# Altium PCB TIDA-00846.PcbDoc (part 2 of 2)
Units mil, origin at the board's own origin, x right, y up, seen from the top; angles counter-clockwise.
Board outline 4950 x 3450 mil, 2 copper layers (Top Layer, Bottom Layer), stack 62 mil thick; 90 components, 50 nets, 307 pads, 480 vias.
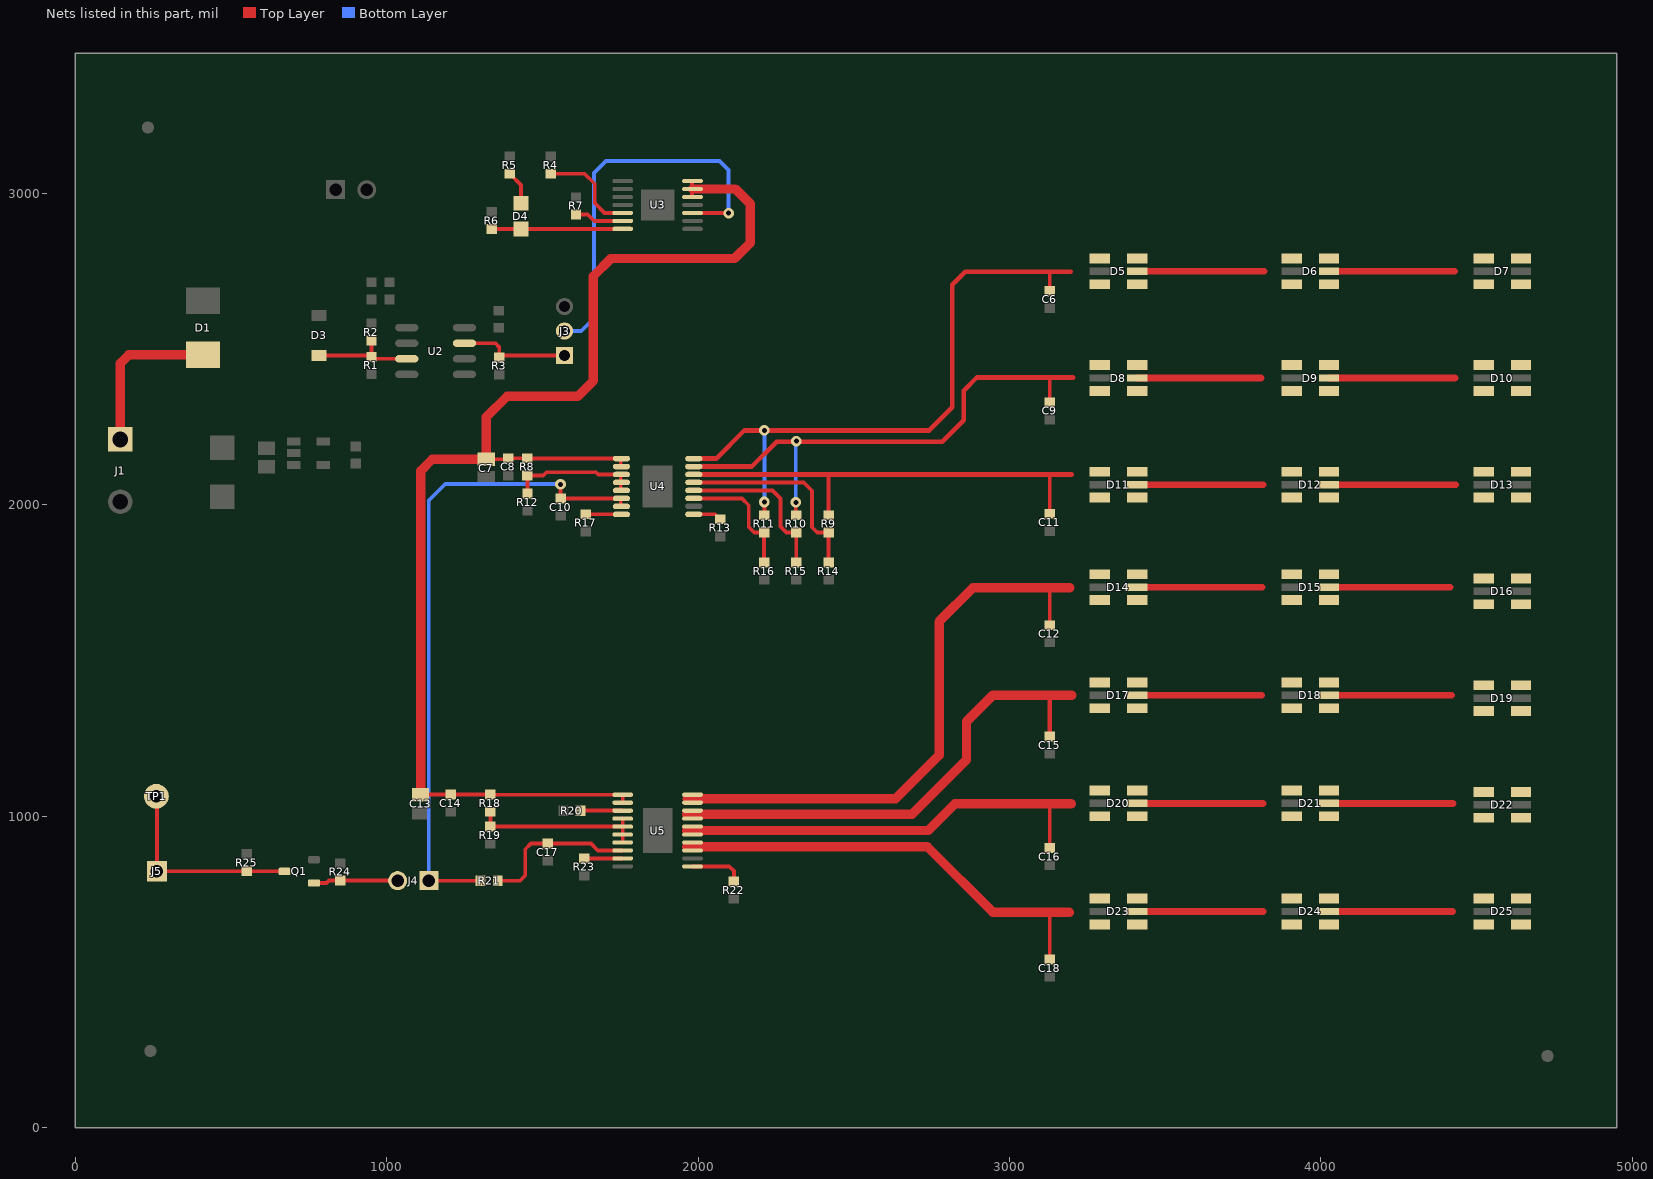
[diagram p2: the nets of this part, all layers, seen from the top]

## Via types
v1: diameter 34, hole 16, Top Layer to Bottom Layer, 455 vias
v2: diameter 15.75, hole 7.87, Top Layer to Bottom Layer, 10 vias
v3: diameter 19.68, hole 7.87, Top Layer to Bottom Layer, 8 vias
v4: diameter 30, hole 18, Top Layer to Bottom Layer, 7 vias

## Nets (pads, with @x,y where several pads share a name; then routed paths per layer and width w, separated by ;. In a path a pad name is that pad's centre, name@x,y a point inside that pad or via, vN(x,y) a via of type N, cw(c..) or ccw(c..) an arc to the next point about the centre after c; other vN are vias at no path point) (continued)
NetC6_1: C6.1 D5.1 D5.3 D5.4 D5.6 R11.2 U4.16 | length 2023.6
  Top Layer w12: R11.2@2212,1966.56 2213,1967.56 v1(2213,2009) ; C6.1@3129,2687.56 3129,2748
  Top Layer w15: U4.16@1986.14,2148.65 2058.65,2148.65 2149,2239 v1(2213,2239) 2742,2239 2816,2313 2816,2707 2858,2749 3197,2749
  Bottom Layer w12: v1(2213,2009) v1(2213,2239)
NetC7_1: C7.1 C8.1 C13.1 C14.1 R8.2 R18.2 U3.5 U3.6 U3.7 U4.1 U4.2 U5.1 U5.2 | length 4121.1
  Top Layer w12: C13.1@1109,1069.53 1205.05,1069.53 C14.1@1205.2,1069.68 1332.88,1069.68 R18.2@1333,1069.56 1333.4,1069.16 U5.1@1757.8,1069.16 ; C7.1@1319.89,2146.61 C7.1@1320,2146.61 ; C7.1@1347.45,2146.61 1386.86,2146.61 C8.1@1389.89,2149.65 1389.98,2149.56 R8.2@1451,2149.56 1451.91,2148.65 U4.1@1751.75,2148.65 ; U4.2@1751.75,2123.06 U4.1@1751.75,2148.65 ; U4.1@1753.86,2148.65 U4.1@1751.75,2148.65 ; U5.2@1757.8,1043.57 1757.8,1062.13 ; U3.5@1980.2,2988.59 U3.7@1980.2,3039.77
  Top Layer w30: C13.1@1109,1091.18 1109,2109 1146.61,2146.61 C7.1@1319.89,2146.61 ; C7.1@1319.89,2168.27 1319.89,2281.89 1387,2349 1614,2349 1663,2398 1663,2734 1720,2791 2117,2791 2168,2842 2168,2966 2119.82,3014.18 U3.6@1982.2,3014.18 ; C7.1@1320,2142.68 C7.1@1320,2146.61
NetC9_1: C9.1 D8.1 D8.3 D8.4 D8.6 R10.2 U4.15 | length 1712.7
  Top Layer w12: v1(2314,2008) 2314,1968.06 R10.2@2315.5,1966.56 ; v1@2314,2203 v1(2315.5,2204.5) ; C9.1@3129,2329.56 3129,2409
  Top Layer w15: U4.15@1986.14,2123.06 2172.06,2123.06 2252,2203 2314,2203 2784,2203 2853,2272 2853,2367 2895,2409 3129,2409 3204,2409
  Bottom Layer w12: v1(2314,2008) 2314,2203 v1(2315.5,2204.5)
NetC10_1: C10.1 J4.1 R21.2 U4.6 U4.7 | length 2085.4
  Top Layer w12: J4.1@1135,793 R21.2@1285.69,793 ; v1(1558,2066) 1558,2021.56 C10.1@1559,2020.56 1559.14,2020.7 U4.6@1751.75,2020.7 ; U4.7@1751.75,1995.11 U4.6@1751.75,2020.7 ; U4.6@1753.86,2020.7 U4.6@1751.75,2020.7
  Bottom Layer w12: J4.1@1135,793 1135,2014 1188,2067 1557,2067 1558,2068 v1(1558,2066)
NetC11_1: C11.1 D11.1 D11.3 D11.4 D11.6 R9.2 U4.14 | length 1469.2
  Top Layer w12: R9.2@2419,1966.56 2419,2096.47 ; C11.1@3129,1971.56 3129,2096.47
  Top Layer w15: U4.14@1986.14,2097.47 3200.53,2097.47
NetC12_1: C12.1 D14.1 D14.3 D14.4 D14.6 U5.19 U5.20 | length 1879.6
  Top Layer w12: C12.1@3129,1613.56 3129,1732
  Top Layer w30: 1965,1056 2634,1056 2774,1196 2774,1625 2883,1734 3194,1734
NetC15_1: C15.1 D17.1 D17.3 D17.4 D17.6 U5.17 U5.18 | length 1597.1
  Top Layer w15: C15.1@3129,1255.56 3129,1385
  Top Layer w30: 1963,1006 2687,1006 2862,1181 2862,1304 2947,1389 3200,1389
NetC16_1: C16.1 D20.1 D20.3 D20.4 D20.6 U5.15 U5.16 | length 1412.1
  Top Layer w12: C16.1@3129,897.56 3129,1039
  Top Layer w30: 1963,954 2739,954 2825,1040 3198,1040
NetC17_1: C17.1 R21.1 U5.8 | length 492.6
  Top Layer w12: R21.1@1356.56,793 1428,793 1445,810 1445,894 1463.56,912.56 C17.1@1500.27,912.56 ; C17.1@1517,912.56 1517.56,912 1656,912 1677.98,890.02 U5.8@1757.8,890.02
NetC18_1: C18.1 D23.1 D23.3 D23.4 D23.6 U5.13 U5.14 | length 1466.8
  Top Layer w12: C18.1@3129,539.56 3129,691
  Top Layer w30: 1964,902 2736,902 2946,692 3191,692 3192,691
NetD1_2: D1.2 J1.1 | length 467.5
  Top Layer w30: J1.1@144.25,2210 144.25,2454.25 171.99,2481.99 D1.2@356,2481.99
NetD3_2: D3.2 R1.1 R2.2 U2.7 | length 330.9
  Top Layer w12: D3.2@783,2479.53 947.03,2479.53 R1.1@951,2475.56 957.56,2469 U2.7@1064.48,2469 ; R1.1@951,2482.43 R2.2@951,2527.44
NetD4_1: D4.1 R5.1 | length 86.4
  Top Layer w12: R5.1@1395,3063.49 1431,3027.49 D4.1@1431,2991.96
NetD4_2: D4.2 R6.1 U3.14 | length 422.2
  Top Layer w10: R6.1@1337,2885.44 R6.1@1337.22,2885.66 ; D4.2@1431,2885.66 D4.2@1431.57,2886.23 ; U3.14@1757.01,2885.44 U3.14@1757.8,2886.23
  Top Layer w12: R6.1@1337.22,2885.66 D4.2@1431,2885.66 ; D4.2@1431.57,2886.23 U3.14@1757.8,2886.23
NetD5_2: D5.2 D6.1 D6.3 D6.4 D6.6 | length 407
  Top Layer w22: D5.2@3410.04,2750 3817,2750
NetD6_2: D6.2 D7.1 D7.3 D7.4 D7.6 | length 403.5
  Top Layer w22: D6.2@4026.54,2750 4430,2750
NetD8_2: D8.2 D9.1 D9.3 D9.4 D9.6 | length 397.3
  Top Layer w22: D8.2@3410.04,2407.33 3807.33,2407.33
NetD9_2: D9.2 D10.1 D10.3 D10.4 D10.6 | length 404.8
  Top Layer w22: D9.2@4026.54,2407.33 4431.33,2407.33
NetD11_2: D11.2 D12.1 D12.3 D12.4 D12.6 | length 403.6
  Top Layer w22: D11.2@3410.04,2064.67 3813.67,2064.67
NetD12_2: D12.2 D13.1 D13.3 D13.4 D13.6 | length 406.1
  Top Layer w22: D12.2@4026.54,2064.67 4432.67,2064.67
NetD14_2: D14.2 D15.1 D15.3 D15.4 D15.6 | length 400.5
  Top Layer w22: D14.2@3410.04,1735.5 3810.5,1735.5
NetD15_2: D15.2 D16.1 D16.3 D16.4 D16.6 | length 389
  Top Layer w22: D15.2@4026.54,1735.5 4415.5,1735.5
NetD17_2: D17.2 D18.1 D18.3 D18.4 D18.6 | length 399.3
  Top Layer w22: D17.2@3410.04,1388.33 3809.33,1388.33
NetD18_2: D18.2 D19.1 D19.3 D19.4 D19.6 | length 393.1
  Top Layer w22: D18.2@4026.54,1388.33 4419.67,1388.33
NetD20_2: D20.2 D21.1 D21.3 D21.4 D21.6 | length 404.1
  Top Layer w22: D20.2@3410.04,1041.17 3814.17,1041.17
NetD21_2: D21.2 D22.1 D22.3 D22.4 D22.6 | length 397.6
  Top Layer w22: D21.2@4026.54,1041.17 4424.17,1041.17
NetD23_2: D23.2 D24.1 D24.3 D24.4 D24.6 | length 405
  Top Layer w22: D23.2@3410.04,694 3815,694
NetD24_2: D24.2 D25.1 D25.3 D25.4 D25.6 | length 396.5
  Top Layer w22: D24.2@4026.54,694 4423,694
NetJ3_1: J3.1 R3.2 U2.3 | length 346.5
  Top Layer w10: R3.2@1361,2473.56 R3.2@1366.7,2479.26
  Top Layer w12: U2.3@1249.52,2519 1349,2519 1361,2507 R3.2@1361,2489.31 ; R3.2@1366.7,2479.26 J3.1@1571,2479.26
NetJ3_2: J3.2 U3.3 | length 1292.1
  Top Layer w12: U3.3@1982.2,2937.41 v1@2097.59,2937.41
  Bottom Layer w12: J3.2@1571,2558 1625,2558 1666,2599 1666,3066 1704,3104 2069,3104 2098,3075 v1(2098,2937)
NetJ4_2: J4.2 Q1.1 R24.1 | length 271.7
  Top Layer w12: Q1.1@766.19,785.52 806.52,785.52 814.44,793.44 R24.1@851,793.44 J4.2@1034.56,793.44
NetJ5_1: J5.1 Q1.3 R25.2 TP1.1 | length 647.6
  Top Layer w12: TP1.1@262.44,1061.56 262.44,823.44 R25.2@550,823.44 550.52,822.92 Q1.3@671.7,822.92
NetR4_1: R4.1 U3.12 | length 317.3
  Top Layer w12: R4.1@1527,3063.49 1635.51,3063.49 1668,3031 1668,2969 1699.59,2937.41 U3.12@1755.8,2937.41
NetR7_1: R7.1 U3.13 | length 141.6
  Top Layer w12: 1624.73,2932.44 1645.56,2932.44 1666.18,2911.82 U3.13@1757.8,2911.82
NetR8_1: R8.1 R12.2 U4.3 U4.4 U4.5 | length 421.1
  Top Layer w12: R12.2@1452.21,2036.65 1452.21,2093.23 R8.1@1451,2094.44 1502.44,2094.44 1513,2105 1672,2105 1679.53,2097.47 U4.3@1753,2097.47 ; U4.5@1751.75,2046.29 1751.75,2097.47 U4.3@1753.86,2097.47
NetR9_1: R9.1 R14.2 U4.13 | length 667.1
  Top Layer w12: U4.13@1984,2071.88 2339.12,2071.88 2366,2045 2366,1928 2382.56,1911.44 R9.1@2419,1911.44 R14.2@2419,1814.31
NetR10_1: R10.1 R15.2 U4.12 | length 502.3
  Top Layer w12: U4.12@1986.14,2046.29 2238.71,2046.29 2265,2020 2265,1930 2283.56,1911.44 R10.1@2298.77,1911.44 ; R15.2@2315.5,1830.31 R10.1@2315.5,1911.44
NetR11_1: R11.1 R16.2 U4.11 | length 376.5
  Top Layer w12: U4.11@1986.14,2020.7 2141.3,2020.7 2163,1999 2163,1929 2180.56,1911.44 R11.1@2195.27,1911.44 ; R16.2@2212,1830.31 R11.1@2212,1911.44
NetR13_2: R13.2 U4.9 | length 91.5
  Top Layer w12: U4.9@1986.14,1969.52 2055.04,1969.52 R13.2@2071,1953.56
NetR17_2: R17.2 U4.8 | length 114.9
  Top Layer w12: R17.2@1639,1969.56 1639.04,1969.52 U4.8@1753.86,1969.52
NetR18_1: R18.1 R19.2 U5.4 U5.5 U5.6 U5.7 | length 526.8
  Top Layer w12: R19.2@1333,966.56 1333.24,966.8 U5.5@1757.8,966.8 ; R19.2@1333,982.31 R18.1@1333,1014.44 ; 1757.8,922.64 U5.6@1757.8,941.2 U5.5@1757.8,966.8 ; U5.4@1757.8,992.39 U5.5@1757.8,966.8
NetR20_2: R20.2 U5.3 | length 135.2
  Top Layer w12: R20.2@1622.56,1018 U5.3@1757.8,1017.98
NetR22_2: R22.2 U5.11 | length 156.6
  Top Layer w12: U5.11@1982.2,838.84 2100.16,838.84 2115,824 R22.2@2115,806.31
NetR23_2: R23.2 U5.9 | length 122.8
  Top Layer w12: R23.2@1635,864.56 1635.13,864.43 U5.9@1757.8,864.43
pads on no net: D5.5 D6.5 D7.5 D8.5 D9.5 D10.5 D11.5 D12.5 D13.5 D14.5 D15.5 D16.5 D17.5 D18.5 D19.5 D20.5 D21.5 D22.5 D23.5 D24.5 D25.5 FID1.1 FID2.1 FID3.1 H1.0 H2.0 H3.0 H4.0 U1.2 U3.1 U3.4 U3.11 U5.10

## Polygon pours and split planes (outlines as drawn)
GND on Top Layer "Top Layer-No Net" (solid, remove dead copper, pour order 4): 0,0 4950,0 4950,3450 0,3450
GND on Bottom Layer "Top Layer-No Net1" (solid, remove dead copper, pour order 6): 0,0 4950,0 4950,3450 0,3450

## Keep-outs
Keep-Out Layer:
  the board outline again, w12
  text ".Layer_Name" at 577,-858.49 h60

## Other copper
Top Layer:
  region net NetC6_1: 3220,2776 3480,2776 3480,2870 3180,2870 3180,2630 3480,2630 3480,2724 3220,2724
  region net NetD5_2: 3840,2776 4100,2776 4100,2870 3800,2870 3800,2630 4100,2630 4100,2724 3840,2724
  region net NetD6_2: 4450,2776 4710,2776 4710,2870 4410,2870 4410,2630 4710,2630 4710,2724 4450,2724
  region net NetC9_1: 3220,2433 3480,2433 3480,2527 3180,2527 3180,2287 3480,2287 3480,2381 3220,2381
  region net NetD8_2: 3830,2433 4090,2433 4090,2527 3790,2527 3790,2287 4090,2287 4090,2381 3830,2381
  region net NetD9_2: 4450,2434 4710,2434 4710,2528 4410,2528 4410,2288 4710,2288 4710,2382 4450,2382
  region net NetC11_1: 3221,2090 3481,2090 3481,2184 3181,2184 3181,1944 3481,1944 3481,2038 3221,2038
  region net NetC16_1: 3220,1068 3480,1068 3480,1162 3180,1162 3180,922 3480,922 3480,1016 3220,1016
  region net NetD17_2: 3830,1414 4090,1414 4090,1508 3790,1508 3790,1268 4090,1268 4090,1362 3830,1362
  region net NetC15_1: 3220,1414 3480,1414 3480,1508 3180,1508 3180,1268 3480,1268 3480,1362 3220,1362
  region net NetD15_2: 4450,1747 4710,1747 4710,1841 4410,1841 4410,1601 4710,1601 4710,1695 4450,1695
  region net NetD14_2: 3840,1762 4100,1762 4100,1856 3800,1856 3800,1616 4100,1616 4100,1710 3840,1710
  region net NetC12_1: 3220,1762 3480,1762 3480,1856 3180,1856 3180,1616 3480,1616 3480,1710 3220,1710
  region net NetC18_1: 3220,720 3480,720 3480,814 3180,814 3180,574 3480,574 3480,668 3220,668
  region net NetD23_2: 3840,720 4100,720 4100,814 3800,814 3800,574 4100,574 4100,668 3840,668
  region net NetD24_2: 4451,720 4711,720 4711,814 4411,814 4411,574 4711,574 4711,668 4451,668
  region net NetD21_2: 4450,1063 4710,1063 4710,1157 4410,1157 4410,917 4710,917 4710,1011 4450,1011
  region net NetD20_2: 3840,1068 4100,1068 4100,1162 3800,1162 3800,922 4100,922 4100,1016 3840,1016
  region net NetD18_2: 4450,1405 4710,1405 4710,1499 4410,1499 4410,1259 4710,1259 4710,1353 4450,1353
  region net NetD12_2: 4451,2092 4711,2092 4711,2186 4411,2186 4411,1946 4711,1946 4711,2040 4451,2040
  region net NetD11_2: 3831,2091 4091,2091 4091,2185 3791,2185 3791,1945 4091,1945 4091,2039 3831,2039
  text ".Layer_Name" at 577,-858.49 h60
Bottom Layer:
  text ".Layer_Name" at 577,-858.49 h60

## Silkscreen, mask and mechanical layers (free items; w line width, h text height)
Top Overlay:
  text "Automotive Highside Dimming Rear Light" at 2334,3032 h50
  text "STOP" at 1679,2625 h30 r90
  text "TAIL" at 1669,2407 h30 r90
  text "Level high - FAULT" at 343,1122 h30
  text "Level low - No FAULT" at 343,1042 h30
  text "TIDA-00846" at 3129,247 h50
  text ".Layer_Name" at 577,-858.49 h30
Bottom Overlay:
  text ".Layer_Name" at 577,-858.49 h60
Top Paste:
  text ".Layer_Name" at 577,-858.49 h60
Bottom Paste:
  text ".Layer_Name" at 577,-858.49 h60
Top Solder:
  text ".Layer_Name" at 577,-858.49 h60
  text ".Layer_Name" at 577,-858.49 h60
Bottom Solder:
  text ".Layer_Name" at 577,-858.49 h60
Drill Guide:
  text ".Layer_Name" at 577,-858.49 h60
M1 Board Outline:
  the board outline again, w10
  text ".Layer_Name" at 577,-858.49 h60
M2 Board Dimensions:
  rectangle: 0,-285.5 125,-160.5
  rectangle: 125,-410.5 500,-285.5
  lines w7: 0,-285.5 1000,-285.5 ; 125,-410.5 125,-160.5 ; 250,-410.5 250,-160.5 ; 500,-410.5 500,-160.5 ; 750,-410.5 750,-160.5 ; 0,-410.5 1000,-410.5 1000,-160.5 0,-160.5 0,-410.5
  text ".Layer_Name" at 577,-858.49 h60
M3 3D STEP Top:
  text ".Layer_Name" at 577,-858.49 h60
M4 3D STEP Bottom:
  text ".Layer_Name" at 577,-858.49 h60
M5 Assembly Top:
  lines w10: -292,-930.17 6308,-930.17 ; -292,-726.83 6310,-726.83 ; -292,-523.5 -292,-1133.5 3713,-1133.5 6310,-1133.5 6310,-523.5 -291.5,-523.5 -291.5,-1133.5 1284,-1133.5 ; 2173,-1133.5 2173,-523.5 ; 3440,-726.83 3440,-523.5 ; 4280,-726.83 4280,-523.5 ; 4902,-1140 4902,-937.17
  text "COMPONENTS MARKED 'DNP' SHOULD NOT BE POPULATED." at 1153.5,-318.5 h60
  text "ASSEMBLY VARIANT:" at 1153,-434 h60
  text ".VariantName" at 2189,-434 h60
  text "PCB VIEWED FROM TOP SIDE" at -228.5,-655.67 h60
  text "BOARD #:" at 2248,-655.67 h60
  text ".PRJ_Number" at 2793.5,-655.67 h60
  text "REV:" at 3638,-655.67 h60
  text ".PCB_Rev" at 3929.5,-655.67 h60
  text "SVN REV:" at 4476,-655.67 h60
  text ".VersionControl_RevNumber" at 4982,-655.67 h60
  text "IGNORE ->" at -228.5,-858.49 h60
  text "PLOT NAME =" at -228.5,-1064.34 h60
  text ".plot_File_Name" at 577,-1064.34 h60
  text "GENERATED    :" at 2250,-1064.34 h60
  text ".Print_Date" at 3119.5,-1064.34 h60
  text ".Print_Time" at 3848.5,-1064.34 h60
  text "TEXAS INSTRUMENTS" at 5113,-1064.34 h60
M6 Assembly Bottom:
  lines w10: -292.5,-727.33 6309.5,-727.33 ; -290.5,-930.67 6309.5,-930.67 ; 1115.5,-1140.5 1115.5,-937.67 ; 1737.5,-727.33 1737.5,-524 ; 2577.5,-727.33 2577.5,-524 ; 3844.5,-1134 3844.5,-524 ; 4733.5,-1134 6309,-1134 6309,-524 -292.5,-524 -292.5,-1134 2304.5,-1134 6309.5,-1134 6309.5,-524
  text "COMPONENTS MARKED 'DNP' SHOULD NOT BE POPULATED." at 6102,-318 h60
  text ".VariantName" at 5058,-434 h60
  text "ASSEMBLY VARIANT:" at 6097,-434 h60
  text ".VersionControl_RevNumber" at 1035.5,-656.17 h60
  text "SVN REV:" at 1541.5,-656.17 h60
  text ".PCB_Rev" at 2088,-656.17 h60
  text "REV:" at 2379.5,-656.17 h60
  text ".PRJ_Number" at 3224,-656.17 h60
  text "BOARD #:" at 3769.5,-656.17 h60
  text "PCB VIEWED FROM BOTTOM SIDE" at 6246,-656.17 h60
  text "IGNORE ->" at 2547.85,-858.49 h60
  text "TEXAS INSTRUMENTS" at 904.5,-1064.84 h60
  text ".Print_Time" at 2169,-1064.84 h60
  text ".Print_Date" at 2898,-1064.84 h60
  text "GENERATED    :" at 3767.5,-1064.84 h60
  text ".plot_File_Name" at 5440.5,-1064.84 h60
  text "PLOT NAME =" at 6246,-1064.84 h60
M9 Title Sheet:
  drawing of 57 lines, arcs and shapes, not listed
  text "1" at 739.84,8036.5 h70
  text "2" at 3235.5,8036.5 h70
  text "3" at 5724.84,8036.5 h70
  text "4" at 8231.51,8036.5 h70
  text "5" at 10730.5,8036.5 h70
  text "6" at 13235.5,8036.5 h70
  text "A" at -416.5,6893.5 h70
  text "A" at 14383.5,6893.5 h70
  text "B" at -416.5,4513.5 h70
  text "B" at 14383.5,4513.5 h70
  text "C" at -416.5,2138.5 h70
  text "C" at 14383.5,2138.5 h70
  text "PROJECT TITLE:" at 11343.5,277.5 h45
  text ".PRJ_Title" at 11393.5,144.17 h70
  text "DESIGNED FOR:" at 11343.5,-23.5 h45
  text ".PRJ_Customer" at 11393.5,-163.5 h70
  text "D" at -416.5,-231.5 h70
  text "D" at 14383.5,-231.5 h70
  text "FILE NAME:" at 11343.5,-323.5 h45
  text ".PCB_File_Name_No_Path" at 11393.5,-443.5 h70
  text "Texas Instruments (TI) and/or its licensors do not warrant the accuracy or completeness of this specification" at 6374,-605.34 h45
  text "ENGINEER:" at 11343.5,-613.5 h45
  text "LAYOUT BY:" at 12848.5,-613.5 h45
  text "or any information contained therein. TI and/or its licensors do not warrant that this design will meet" at 6329.01,-718 h45
  text ".PRJ_Engineer" at 11393.5,-768.49 h70
  text ".PCB_Layout" at 12899,-768.49 h70
  text "the specifications, will be suitable for your application or fit for any particular purpose, or will operate in" at 6329.01,-830.67 h45
  text ".Layer_Name" at 577,-858.49 h60
  text "ALTIUM DESIGNER VERSION:" at 12848.5,-923.5 h45
  text "an implementation. TI and/or its licensors do not warrant that the design is production worthy. You should" at 6329.01,-943.33 h45
  text "completely validate and test your design implementation to confirm the system functionality for your application." at 6374,-1056 h45
  text ".print_Scale" at 11393.5,-1056.83 h70
  text ".Application_BuildNumber" at 12899,-1056.83 h70
  text "1" at 739.84,-1263.5 h70
  text "2" at 3235.5,-1263.5 h70
  text "3" at 5724.84,-1263.5 h70
  text "4" at 8231.51,-1263.5 h70
  text "5" at 10730.5,-1263.5 h70
  text "6" at 13235.5,-1263.5 h70
M10 Fab Notes:
  drawing of 185 lines, arcs and shapes, not listed
  text "DESIGN INFORMATION" at 12381.02,5910 h60
  text "MIN. TRACK WIDTH:" at 11736.46,5730 h60
  text "8" at 12832.7,5730 h60
  text "MIL" at 12987.46,5730 h60
  text "MIN. CLEARANCE:" at 11736.46,5598 h60
  text "0.2" at 12772.7,5598 h60
  text "mm" at 12987.46,5598 h60
  text "MIN. VIA PAD SIZE:" at 11736.46,5466 h60
  text "24" at 12802.71,5466 h60
  text "MIL" at 12987.46,5466 h60
  text "0.05mm (2MIL)" at 12431.46,5324.29 h60
  text "MINIMUM ANNULAR RING" at 11407.23,5320 h60
  text "EXTERNAL" at 13139.46,5320 h60
  text "PER" at 11607.23,5202 h60
  text "IPC-D-275 CLASS 2 LEVEL C" at 11827.23,5202 h60
  text "MIL, HOLES" at 13315.46,5089.71 h60
  text "+/-" at 12923,5089 h60
  text "+/-" at 13777,5089 h60
  text "REGISTRATION TOLERANCES:" at 11407.23,5084 h60
  text "METAL" at 12607,5084 h60
  text "5" at 13183.2,5084 h60
  text "3" at 14016.2,5084 h60
  text "MIL" at 14132.46,5084 h60
  text "MATERIAL:" at 11332.46,4874.54 h60
  text "FR-4 High Tg" at 12318.9,4734.21 h60
  text "FR-408" at 11753.46,4725.64 h60
  text "X" at 12165.46,4725.64 h60
  text "OTHER" at 13241.46,4725.64 h60
  text "62 MIL (1.6mm) +/-10%" at 12073.56,4562.92 h60
  text "THICKNESS:" at 11407.23,4558.64 h60
  text "X" at 11945.4,4558.64 h60
  text "OTHER" at 13358.46,4558.64 h60
  text "TOLERANCE:" at 11407.23,4400.64 h60
  text "X" at 12246.53,4400.64 h60
  text "ANSI IPC-6012 TYPE 3 CLASS 2" at 12433.48,4400.64 h60
  text "OTHER +/-" at 12433.46,4244.64 h60
  text "BOW & TWIST:" at 11407.23,4087.64 h60
  text "X" at 12246.53,4087.64 h60
  text "ANSI IPC-6012 TYPE 3 CLASS 2" at 12433.48,4087.64 h60
  text "OTHER +/-" at 12433.46,3929.13 h60
  text "DRILLING:" at 11332.46,3790.64 h60
  text "REFERENCE:" at 11407.23,3673.64 h60
  text "X" at 12055.46,3673.64 h60
  text "AS SHOWN" at 12242.46,3673.64 h60
  text "X" at 12956.46,3673.64 h60
  text "NC_DRILL FILES" at 13093.46,3673.64 h60
  text "PTH MIN COPPER THICKNESS:" at 11407.23,3515.64 h60
  text "X" at 12757.46,3515.64 h60
  text "1MIL" at 12894.46,3515.64 h60
  text "OTHER" at 13391.46,3515.64 h60
  text "BOARD FINISH:" at 11332.46,3356.64 h60
  text "SILKSCREEN:" at 11487.68,3238.64 h60
  text "X" at 12436.46,3238.64 h60
  text "TOP" at 12562.46,3238.64 h60
  text "X" at 12946.46,3238.64 h60
  text "BOTTOM" at 13073.46,3238.64 h60
  text "SILKSCREEN COLOR:" at 11487.68,3071.64 h60
  text "X" at 12435.42,3071.64 h60
  text "WHITE" at 12562.46,3071.64 h60
  text "OTHER" at 13073.46,3071.64 h60
  text "SOLDER RESIST COLOR:" at 11487.68,2901.64 h60
  text "X" at 12055.42,2742.44 h60
  text "GREEN" at 12182.46,2742.44 h60
  text "BLUE" at 12773.46,2742.44 h60
  text "OTHER" at 13311.46,2742.44 h60
  text "IMMERSION GOLD (ENIG)" at 12393.46,2553.92 h60
  text "ENEPIG" at 13731,2550.64 h60
  text "SURFACE FINISH:" at 11332.46,2549.64 h60
  text "X" at 12206.51,2549.64 h60
  text "IMM. TIN/SILVER OR EQUIV" at 11662,2392.64 h60
  text "OTHER" at 13093.46,2392.64 h60
  text "ARRAY/PANEL:" at 11332.46,2213.64 h60
  text "CUT AND TRIM PER MECH LAYER 1" at 12393.46,2209.35 h60
  text "N.C. ROUTE" at 12393.46,2057.64 h60
  text "X" at 13072.46,2057.64 h60
  text "V. SCORE" at 13259.46,2057.64 h60
  text "CERTIFICATION:" at 11332.46,1920.64 h60
  text "MATERIALS AND WORKMANSHIP FOR ALL PCBS" at 12057.46,1920.64 h60
  text "TO MEET OR EXCEED THE REQUIREMENTS OF:" at 12057.46,1822.64 h60
  text "X" at 11683.96,1686.13 h60
  text "ANSI IPC-A-600F CLASS ->" at 11822.96,1686.13 h60
  text "X" at 13462.02,1686.13 h60
  text "2" at 13580.96,1686.14 h60
  text "1" at 13265.96,1684.64 h60
  text "3" at 13934.96,1684.64 h60
  text "X" at 11686.02,1526.64 h60
  text "UL 94V-0" at 11822.96,1526.64 h60
  text "X" at 12498.02,1526.64 h60
  text "RoHS" at 12634.96,1526.64 h60
  text "OTHER" at 13279.36,1526.64 h60
  text "PER ORDER" at 13676.42,1526.64 h60
  text "ADDITIONAL REQUIREMENTS:" at 11332.46,1385.64 h60
  text "MICROSECTION:" at 11407.23,1270.64 h60
  text "YES" at 12312.96,1270.64 h60
  text "REQUIRED" at 13174.46,1114.49 h60
  text "BARE BOARD ELEC. TEST:" at 11407.23,1111.64 h60
  text "NONE" at 12712.96,1111.64 h60
  text "X" at 13047.46,1111.64 h60
  text "PER ORDER" at 13766.46,1111.64 h60
  text "MANUFACTURER'S UL:" at 11407.23,954.64 h60
  text "RAIL" at 12572.96,950.35 h60
  text "METAL" at 13064.77,950.35 h60
  text "X" at 13440,950 h60
  text "SILK" at 13576.46,950.35 h60
  text ".Layer_Name" at 577,-858.49 h60
M11 Gerber Information:
  lines w10: -292,-930.17 6308,-930.17 ; -292,-726.83 6310,-726.83 ; -292,-523.5 -292,-1133.5 3713,-1133.5 6310,-1133.5 6310,-523.5 -291.5,-523.5 -291.5,-1133.5 1284,-1133.5 ; 2173,-1133.5 2173,-523.5 ; 3440,-726.83 3440,-523.5 ; 4280,-726.83 4280,-523.5 ; 4902,-1140 4902,-937.17
  text "ALL ARTWORK VIEWED FROM TOP SIDE" at -228.5,-655.67 h60
  text "BOARD #:" at 2248,-655.67 h60
  text ".PRJ_Number" at 2793.5,-655.67 h60
  text "REV:" at 3638,-655.67 h60
  text ".PCB_Rev" at 3929.5,-655.67 h60
  text "SVN REV:" at 4476,-655.67 h60
  text ".VersionControl_RevNumber" at 4982,-655.67 h60
  text "LAYER NAME =" at -228.5,-858.49 h60
  text "PLOT NAME =" at -228.5,-1064.34 h60
  text ".plot_File_Name" at 577,-1064.34 h60
  text "GENERATED    :" at 2250,-1064.34 h60
  text ".Print_Date" at 3119.5,-1064.34 h60
  text ".Print_Time" at 3848.5,-1064.34 h60
  text "TEXAS INSTRUMENTS" at 5113,-1064.34 h60
M12 Stackup:
  lines w6: 11360,7460 13910,7460 ; 11360,7564.4 13910,7564.4 ; 11300,6975 ccw(c11334,6975) 11334,6941 13936,6941 ccw(c13936,6975) 13970,6975 13970,7681 ccw(c13936,7681) 13936,7715 11334,7715 ccw(c11334,7681) 11300,7681 11300,6975
  text "The Stackup Legend below this is static." at 11605.5,7874.5 h60
  text "If you change the stackup, update the Legend." at 11615.5,7784.5 h60
  text "Layer Stack Up Detail for: Ref_Design.PcbDoc" at 11360,7597.1 h57
  text "Layer" at 11360,7525.4 h24
  text "Gerber" at 12255.81,7525.4 h24
  text "Copper" at 12819.33,7525.4 h24
  text "Dielectric" at 13422.04,7525.4 h24
  text "Name" at 11360,7477.4 h24
  text "Document" at 12255.81,7477.4 h24
  text "Thickness" at 12819.33,7477.4 h24
  text "Material" at 13422.04,7477.4 h24
  text "Top Solder Mask" at 11360,7384.44 h34
  text "(.GTS)" at 12255.81,7384.44 h34
  text "Solder Resist" at 13422.04,7384.44 h34
  text "Top Layer" at 11360,7287.69 h34
  text "(.GTL)" at 12255.81,7287.69 h34
  text "1.4mil" at 12819.33,7287.69 h34
  text "FR-4" at 13422.04,7239.31 h34
  text "Bottom Layer" at 11360,7190.94 h34
  text "(.GBL)" at 12255.81,7190.94 h34
  text "1.4mil" at 12819.33,7190.94 h34
  text "Bottom Solder Mask" at 11360,7094.19 h34
  text "(.GBS)" at 12255.81,7094.19 h34
  text "Solder Resist" at 13422.04,7094.19 h34
  text ".Layer_Name" at 577,-858.49 h60
M13 Component Bodies Top:
  text ".Layer_Name" at 577,-858.49 h60
M14 Component Bodies Bottom:
  text ".Layer_Name" at 577,-858.49 h60
M15 Courtyards Top:
  text ".Layer_Name" at 577,-858.49 h60
M16 Courtyards Bottom:
  text ".Layer_Name" at 577,-858.49 h60
Drill Drawing:
  text ".legend" at 5432.5,3375.5 h60
  text "Drill Table" at 5457.5,3190.5 h60
  text ".Layer_Name" at 577,-858.49 h60

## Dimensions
0,0 to 0,3450 on M2 Board Dimensions
0,0 to 4950,0 on M2 Board Dimensions
0,-410.5 to 1000,-410.5 on M2 Board Dimensions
